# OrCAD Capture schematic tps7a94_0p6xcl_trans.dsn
size A
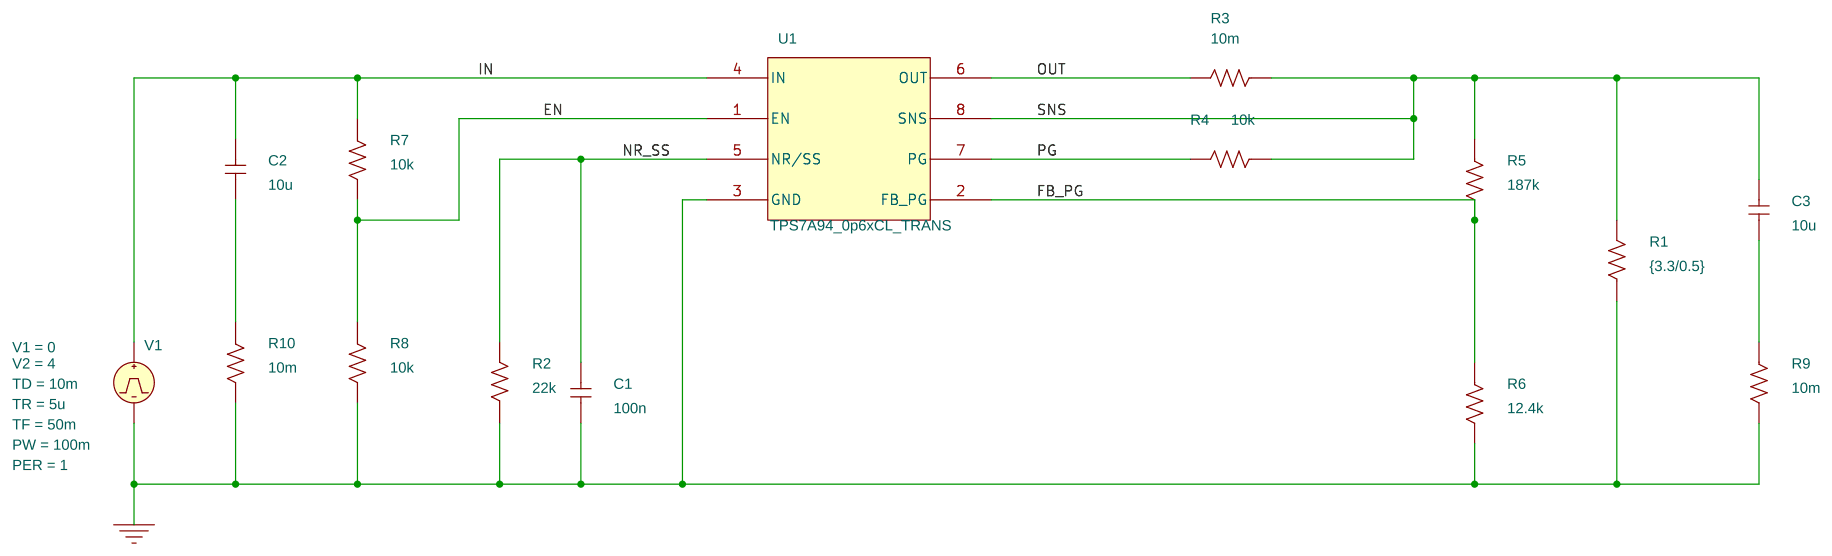
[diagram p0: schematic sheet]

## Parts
C1  100n  [RAD/CK05]
C2  10u  [RAD/CK05]
C3  10u  [RAD/CK05]
R1  {3.3/0.5}  [AX/RC05]
R2  22k  [AX/RC05]
R3  10m  [AX/RC05]
R4  10k  [AX/RC05]
R5  187k  [AX/RC05]
R6  12.4k  [AX/RC05]
R7  10k  [AX/RC05]
R8  10k  [AX/RC05]
R9  10m  [AX/RC05]
R10  10m  [AX/RC05]
U1  TPS7A94_0p6xCL_TRANS
V1  VPULSE

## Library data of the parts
C1-C3 = C
R1-R10 = R
U1 = TPS7A94_600MADC_TRANS_0
V1 = VPULSE: PER: 1; PW: 100m; TD: 10m; TF: 50m; TR: 5u; V1: 0; V2: 4

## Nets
0: C1.1 R1.1 R2.1 R6.2 R8.2 R9.2 R10.2 U1.3(GND) V1.2(-)
EN: R7.2 R8.1 U1.1(EN)
FB_PG: R5.2 R6.1 U1.2(FB_PG)
IN: C2.2 R7.1 U1.4(IN) V1.1(+)
NR_SS: C1.2 R2.2 U1.5(NR/SS)
OUT: R3.2 U1.6(OUT)
PG: R4.2 U1.7(PG)
SNS: C3.2 R1.2 R3.1 R4.1 R5.1 U1.8(SNS)
N240913: C2.1 R10.1
N241023: C3.1 R9.1
